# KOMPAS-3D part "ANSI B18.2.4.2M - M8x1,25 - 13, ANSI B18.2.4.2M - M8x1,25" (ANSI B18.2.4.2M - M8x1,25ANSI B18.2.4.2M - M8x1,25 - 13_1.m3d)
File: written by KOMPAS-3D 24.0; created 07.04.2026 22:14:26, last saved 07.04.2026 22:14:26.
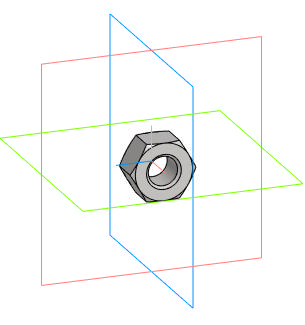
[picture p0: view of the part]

Document properties: Автор: Main; Полное имя файла: D:\DN.ru Аутсерс\Стекло смотровое DN.ru\Исходники\Стекло смотровое DN.ru SG2-34G-F тип В ГОСТ 21836-2021 Ду80 Ру16, углеродистая сталь, фланцевое\ANSI B18.2.4.2M - M8x1,25ANSI B18.2.4.2M - M8x1,25 - 13_1.m3d

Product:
- Body: Solid1  | qty 1
- Part/product: ANSI B18.2.4.2M - M8x1,25 - 13  | designation ANSI B18.2.4.2M - M8x1,25
    Комментарий: Типы метрических   шестигранных гаек   2
    additional columns: Сталь, мягкая

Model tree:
1. Solid1  (labels: Solid1)

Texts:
  ANSI B18.2.4.2M - M8x1,25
